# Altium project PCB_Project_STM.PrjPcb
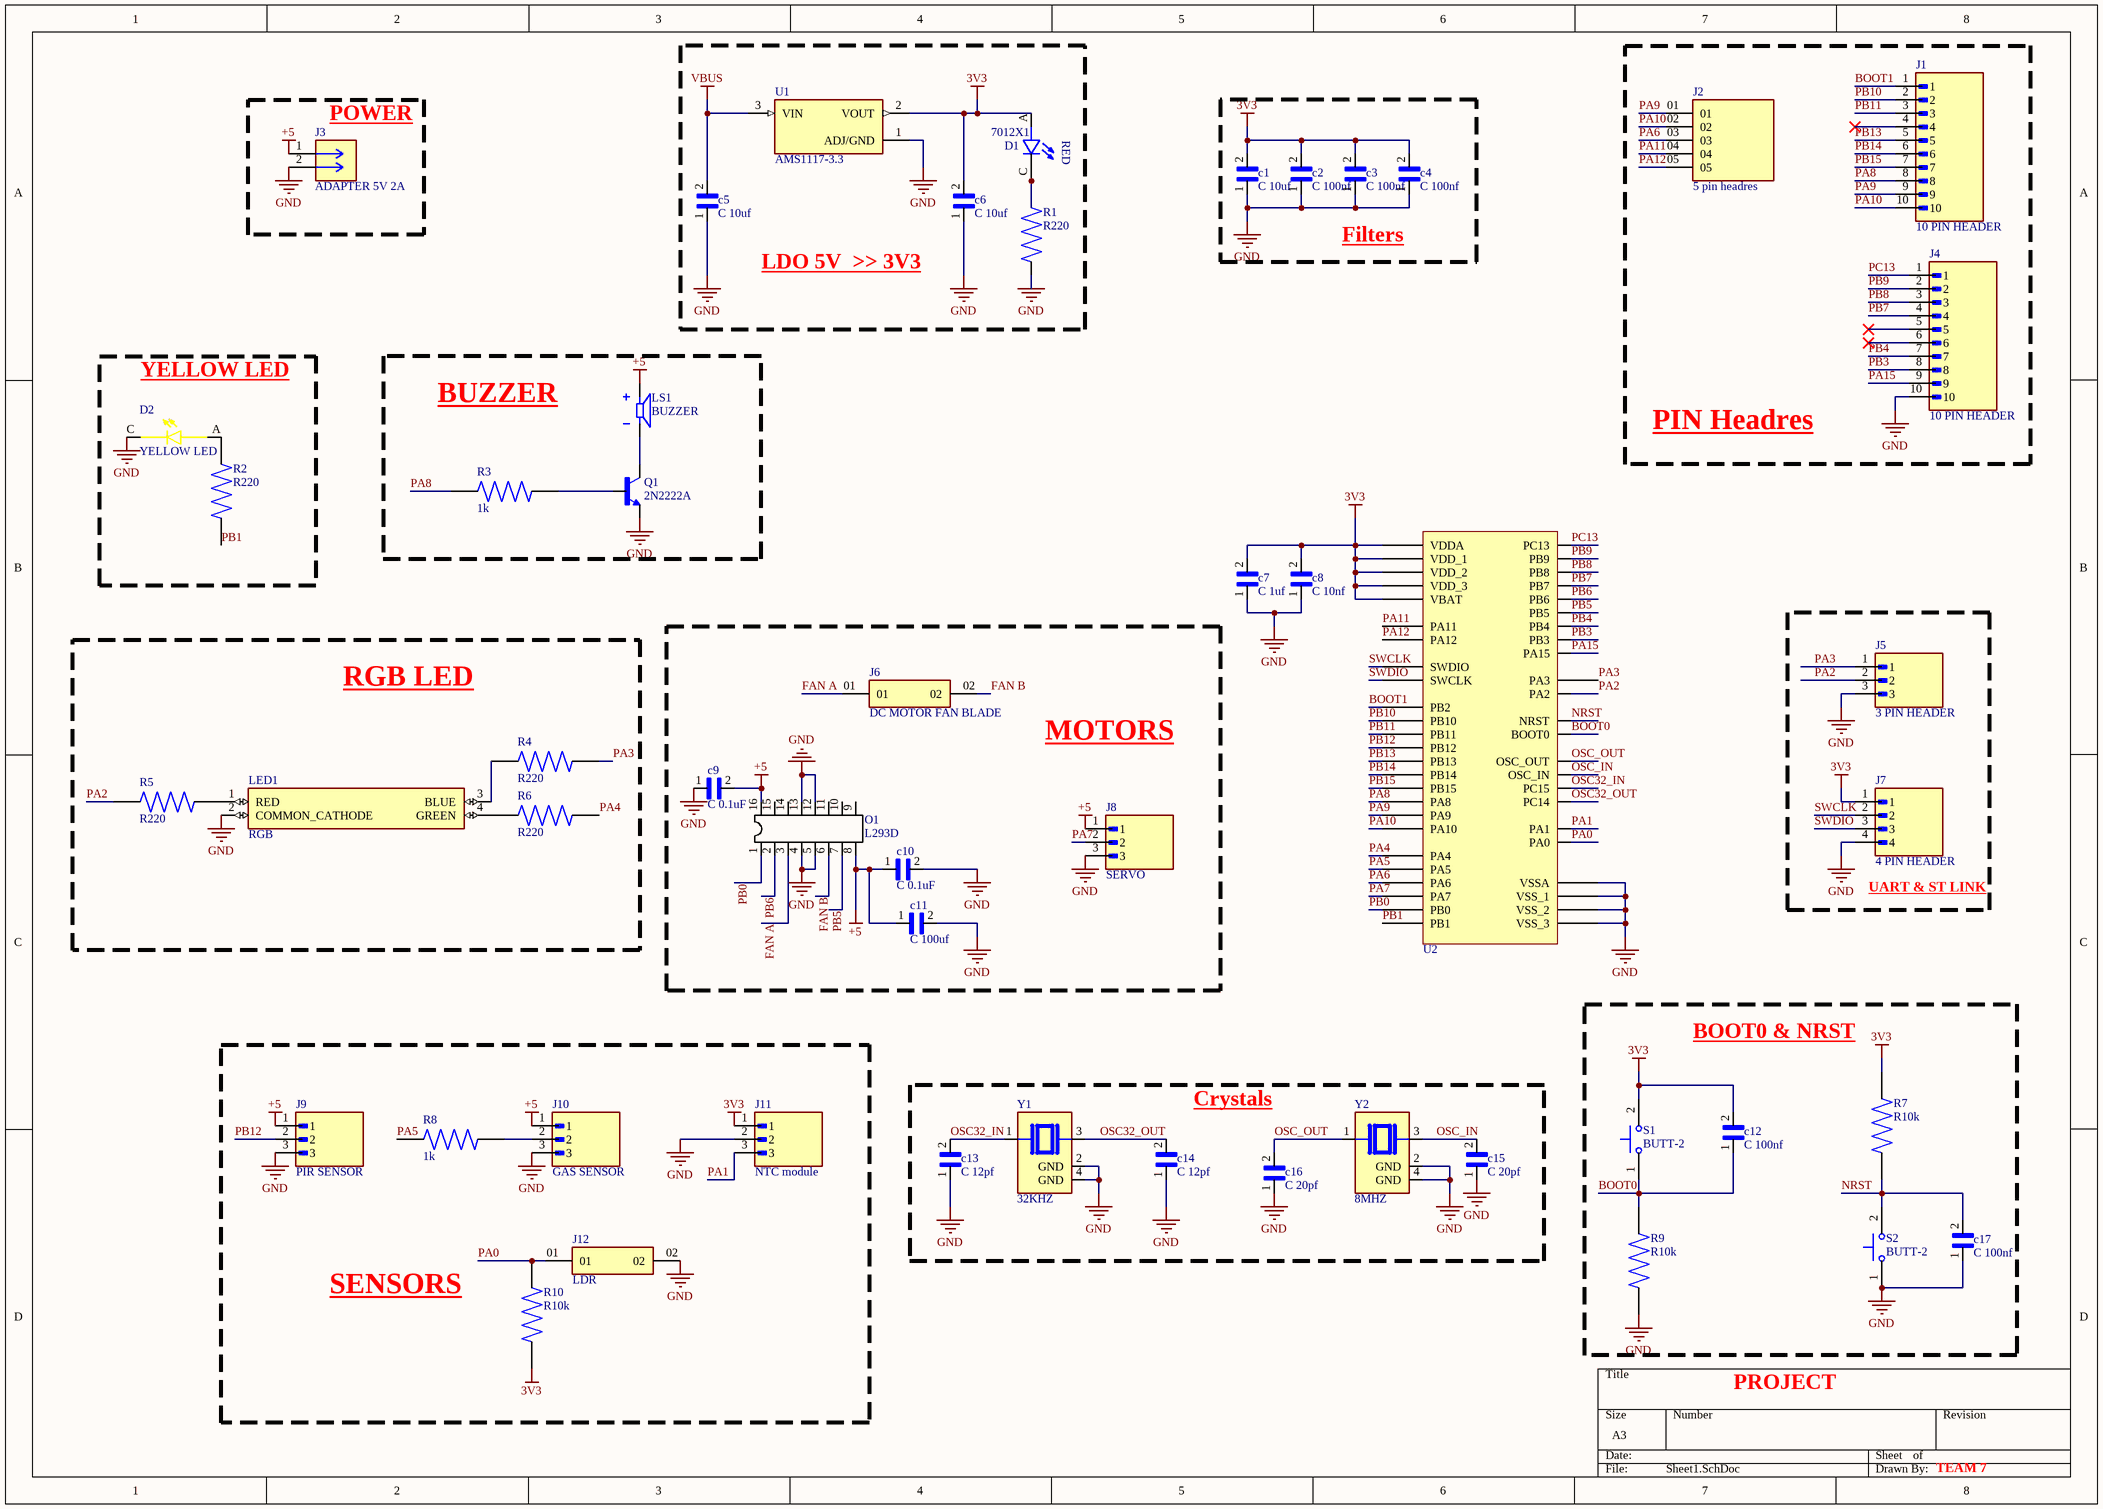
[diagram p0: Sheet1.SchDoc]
1 sheet, 51 parts. Net scope: global (net labels, ports and power ports of the same name join across sheets).
Board file: PCB1.PcbDoc

## Sheet Sheet1.SchDoc
size A3; SheetNumber: 1; SheetTotal: 1

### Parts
c1  C 10uf  [CAPC1608X90]
c2  C 100nf  [CAPC1608X90]
c3  C 100nf  [CAPC1608X90]
c4  C 100nf  [CAPC1608X90]
c5  C 10uf  [CAPC1608X90]
c6  C 10uf  [CAPC1608X90]
c7  C 1uf  [CAPC1608X90]
c8  C 10nf  [CAPC1608X90]
c9  C 0.1uF  [CAPC1608X90]
c10  C 0.1uF  [CAPC1608X90]
c11  C 100uf  [CAPC1608X90]
c12  C 100nf  [CAPC1608X90]
c13  C 12pf  [CAPC1608X90]
c14  C 12pf  [CAPC1608X90]
c15  C 20pf  [CAPC1608X90]
c16  C 20pf  [CAPC1608X90]
c17  C 100nf  [CAPC1608X90]
D1  7012X1  [LED_7012X1]
D2  YELLOW LED  [LED_7012X1]
J1  10 PIN HEADER  [HARWIN_M22-2511005]
J2  5 pin headres  [SAMTEC_TMS-105-53-G-S]
J3  ADAPTER 5V 2A  [CONN2_0393800102_524X492_MOL]
J4  10 PIN HEADER  [HARWIN_M22-2511005]
J5  3 PIN HEADER  [HARWIN_M20-9990346]
J6  DC MOTOR FAN BLADE  [SAMTEC_MTSW-101-09-L-D-515]
J7  4 PIN HEADER  [HARWIN_M20-9990446]
J8  SERVO  [HARWIN_M20-9990346]
J9  PIR SENSOR  [HARWIN_M20-9990346]
J10  GAS SENSOR  [HARWIN_M20-9990346]
J11  NTC module  [HARWIN_M20-9990346]
J12  LDR  [SAMTEC_MTSW-101-09-L-D-515]
LED1  RGB  [L-154A4SUREQBFZGEC]
LS1  BUZZER  [XDCR_CMI-1210-5-95T]
O1  L293D  [DIP880W50P254L2000H510Q16]
Q1  2N2222A  [TO92254P470H750-3]
R1  R220  [RESC1608X55N]
R2  R220  [RESC1608X55N]
R3  1k  [RESC1608X55N]
R4  R220  [RESC1608X55N]
R5  R220  [RESC1608X55N]
R6  R220  [RESC1608X55N]
R7  R10k  [RESC1608X55N]
R8  1k  [RESC1608X55N]
R9  R10k  [RESC1608X55N]
R10  R10k  [RESC1608X55N]
S1  BUTT-2  [SW_BUTT-2]
S2  BUTT-2  [SW_BUTT-2]
U1  AMS1117-3.3  [SOT229P700X180-4N]
U2  ST STM32F103C8T6  [STM]  (value not drawn)
Y1  32KHZ  [XTAL_ABMM2-8.000MHZ-E2-T]
Y2  8MHZ  [XTAL_ABMM2-8.000MHZ-E2-T]

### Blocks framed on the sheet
LDO 5V  >> 3V3: c5 c6 D1 R1 U1
PIN Headres: J1 J2 J4
POWER: J3
Filters: c1-c4
YELLOW LED: D2 R2
BUZZER: LS1 Q1 R3
RGB LED: LED1 R4-R6
MOTORS: c9-c11 J6 J8 O1
UART & ST LINK: J5 J7
BOOT0 & NRST: c12 c17 R7 R9 S1 S2
SENSORS: J9-J12 R8 R10
Crystals: c13-c16 Y1 Y2

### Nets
3V3: c1.2 c2.2 c3.2 c4.2 c6.2 c7.2 c8.2 c12.2 D1.A J7.1 J11.1 R7.2 R10.1 S1.2 U1.2(VOUT) U2.1(VBAT) U2.9(VDDA) U2.24(VDD_1) U2.36(VDD_2) U2.48(VDD_3)
+5: c9.2 c10.1 c11.1 J3.1 J8.1 J9.1 J10.1 LS1.P O1.8(VCC_2) O1.16(VCC_1)
GND: c1.1 c2.1 c3.1 c4.1 c5.1 c6.1 c7.1 c8.1 c9.1 c10.2 c11.2 c13.1 c14.1 c15.1 c16.1 c17.1 D2.C J3.2 J4.10 J5.3 J7.4 J8.3 J9.3 J10.3 J11.2 J12.02 LED1.2(COMMON_CATHODE) O1.4(GND) O1.5(GND) O1.12(GND) O1.13(GND) Q1.1(E) R1.1 R9.1 S2.1 U1.1(ADJ/GND) U2.8(VSSA) U2.23(VSS_1) U2.35(VSS_2) U2.47(VSS_3) Y1.2(GND) Y1.4(GND) Y2.2(GND) Y2.4(GND)
VBUS: c5.2 U1.3(VIN)
BOOT0: c12.1 R9.2 S1.1 U2.44(BOOT0)
BOOT1: J1.1 U2.20(PB2)
FAN A: J6.01 O1.3(OUTPUT_1)
FAN B: J6.02 O1.6(OUTPUT_2)
NRST: c17.2 R7.1 S2.2 U2.7(NRST)
OSC32_IN: c13.2 U2.4(PC15) Y1.1
OSC32_OUT: c14.2 U2.3(PC14) Y1.3
OSC_IN: c15.2 U2.5(OSC_IN) Y2.3
OSC_OUT: c16.2 U2.6(OSC_OUT) Y2.1
PA0: J12.01 R10.2 U2.10(PA0)
PA1: J11.3 U2.11(PA1)
PA2: J5.2 R5.1 U2.12(PA2)
PA3: J5.1 R4.2 U2.13(PA3)
PA4: R6.2 U2.14(PA4)
PA5: R8.1 U2.15(PA5)
PA6: J2.03 U2.16(PA6)
PA7: J8.2 U2.17(PA7)
PA8: J1.8 R3.1 U2.29(PA8)
PA9: J1.9 J2.01 U2.30(PA9)
PA10: J1.10 J2.02 U2.31(PA10)
PA11: J2.04 U2.32(PA11)
PA12: J2.05 U2.33(PA12)
PA15: J4.9 U2.38(PA15)
PB0: O1.1(ENABLE_1,2) U2.18(PB0)
PB1: R2.2 U2.19(PB1)
PB3: J4.8 U2.39(PB3)
PB4: J4.7 U2.40(PB4)
PB5: O1.7(INPUT_2) U2.41(PB5)
PB6: O1.2(INPUT_1) U2.42(PB6)
PB7: J4.4 U2.43(PB7)
PB8: J4.3 U2.45(PB8)
PB9: J4.2 U2.46(PB9)
PB10: J1.2 U2.21(PB10)
PB11: J1.3 U2.22(PB11)
PB12: J9.2 U2.25(PB12)
PB13: J1.5 U2.26(PB13)
PB14: J1.6 U2.27(PB14)
PB15: J1.7 U2.28(PB15)
PC13: J4.1 U2.2(PC13)
SWCLK: J7.2 U2.34(SWDIO)
SWDIO: J7.3 U2.37(SWCLK)
NetD1_C: D1.C R1.2
NetD2_A: D2.A R2.1
NetJ10_2: J10.2 R8.2
NetLED1_1: LED1.1(RED) R5.2
NetLED1_3: LED1.3(BLUE) R4.1
NetLED1_4: LED1.4(GREEN) R6.1
NetLS1_N: LS1.N Q1.3(C)
NetQ1_2: Q1.2(B) R3.2

Not connected (* = marked no-connect by the designer): J1 4*; J4 5* 6*; O1 9(Enable_3,4) 10(INPUT_3) 11(OUTPUT_3) 14(OUTPUT_4) 15(INPUT_4)

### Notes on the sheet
- PROJECT
- TEAM 7

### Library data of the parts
c1 c5 c6 = C 10uf: 10uF Â±10% 50V Ceramic Capacitor X7R 0603 (1608 Metric); MF: KEMET; MP: C0603X102K5RAC3316
c2-c4 c12 c17 = C 100nf: 100nF Â±10% 50V Ceramic Capacitor X7R 0603 (1608 Metric); MF: KEMET; MP: C0603X102K5RAC3316
c7 = C 1uf: 1uF Â±10% 50V Ceramic Capacitor X7R 0603 (1608 Metric); MF: KEMET; MP: C0603X102K5RAC3316
c8 = C 10nf: 10nF Â±10% 50V Ceramic Capacitor X7R 0603 (1608 Metric); MF: KEMET; MP: C0603X102K5RAC3316
c9 c10 = C 0.1uF: 0.1uFÂ±10% 50V Ceramic Capacitor X7R 0603 (1608 Metric); MF: KEMET; MP: C0603X102K5RAC3316
c11 = C 100uf: 100uf Â±10% 50V Ceramic Capacitor X7R 0603 (1608 Metric); MF: KEMET; MP: C0603X102K5RAC3316
c13 c14 = C 12pf: 12PF Â±10% 50V Ceramic Capacitor X7R 0603 (1608 Metric); MF: KEMET; MP: C0603X102K5RAC3316
c15 c16 = C 20pf: 20PF Â±10% 50V Ceramic Capacitor X7R 0603 (1608 Metric); MF: KEMET; MP: C0603X102K5RAC3316
D1 = 7012X1: Red - LED Indication - Discrete 1.7V 0805 (2012 Metric); MNF PART: YLED0603R; SUP PART: C19171390; MNF: YONGYUTAI
D2 = YELLOW LED: Red 617nm Yellow LED Indication - Discrete 2V Radial; MP: WP7113ID; MF: Kingbright
J1 J4 = 10 PIN HEADER: 2.00mm (0.079") Pitch SIL Vertical 2.4mm Throughboard Pin Header, 3.5mm mating pin height, gold, 10 contacts; MF: {'manufacturer': u'Harwin Inc.'}; MP: M22-2511005
J2 = 5 pin headres: MP: TMS-105-53-G-S
J3 = Power place: 2 Position Wire to Board Terminal Block Horizontal with Board 0.250" (6.35mm) Through Hole; MP: 393800102
J5 J8-J11 = 3 PIN HEADER: 2.54mm (0.1) Pitch SIL Vertical Throughboard Pin Header, 6.1mm mating pin height, tin, 3 contacts; MF: Harwin; MP: M20-9990346
J6 J12 = 2 pin Headers: Suoolier part number: 952-1902-ND; Manufacturer: Harwin; MP: MTSW-101-09-L-D-515
J7 = 4 Pin headers: 1kV 1 2.54mm Pin Header 3A 2.5mm Through Hole 6mm -40℃~+105℃ 3mm Gold 4P 1x4P Through Hole,P=2.54mm Headers, Male Pins; MF: Harwin; MP: M20-9990446
LED1 = RGB: Red, Green, Blue (RGB) 630nm Red, 525nm Green, 465nm Blue LED Indication - Discrete 1.9V Red, 3.3V Green, 3.3V Blue Radial - 4 Leads; MF: Kingbright; MP: WP154A4SUREQBFZGW
LS1 = BUZZER: 12 mm, 5 Vdc, 98 dB, Through Hole, Magnetic Audio Indicator Buzzer; MF: Same Sky; MP: CMI-1210-5-95T
Q1 = 2N2222A: BJT, TO-92, 40V, 600mA, NPN, 0.625W, 150Â°C; MF: Diotec Semiconductor
R1 R2 R4-R6 = R220: RES, 220OHM, 1%, 0.1W, 0603, THICK FILM; Resistance: 10kohm; Resistance Tolerance: Â± 1%; Power Rating: 100mW; Resistor Case / Package: 0603 ^1608 Metric]; Resistor Technology: Thick Film; Resistor Type: Genera 67AK7947; MF: Vishay Intertechnology; MP: CRCW060310K0FKECC
R3 R8 = 1k: RES, 1K, 1%, 0.1W, 0603, THICK FILM; Resistance: 10kohm; Resistance Tolerance: Â± 1%; Power Rating: 100mW; Resistor Case / Package: 0603 ^1608 Metric]; Resistor Technology: Thick Film; Resistor Type: Genera 67AK7947; MF: Vishay Intertechnology; MP: CRCW060310K0FKECC
R7 R9 R10 = R10k: RES, 10K, 1%, 0.1W, 0603, THICK FILM; Resistance: 10kohm; Resistance Tolerance: Â± 1%; Power Rating: 100mW; Resistor Case / Package: 0603 ^1608 Metric]; Resistor Technology: Thick Film; Resistor Type: Genera 67AK7947; MF: Vishay Intertechnology; MP: CRCW060310K0FKECC
S1 S2 = BUTT-2: Tactile Switches MINI PUSH BUTTON SWITCH 2-PIN QTY. 4; MF: Gravitech
U1 = AMS1117-3.3: Linear Voltage Regulator IC Positive Fixed 1 Output 1A SOT-223-3L; MF: UMW
U2 = ST STM32F103C8T6: Medium-density performance line Arm-based 32-bit MCU with 64 or 128 KB Flash, USB, CAN, 7 timers, 2 ADCs, 9 com. interfaces
Y1 = CRYSTAL 32KHZ: 32KHz Â±20ppm Crystal 12.5pF 72 Ohms 4-SMD, No Lead; MP: ABMM2-8.000MHZ-E2-T; MF: Abracon
Y2 = CRYSTAL 8MHZ: 8 MHz Â±20ppm Crystal 18pF 72 Ohms 4-SMD, No Lead; MP: ABMM2-8.000MHZ-E2-T; MF: Abracon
